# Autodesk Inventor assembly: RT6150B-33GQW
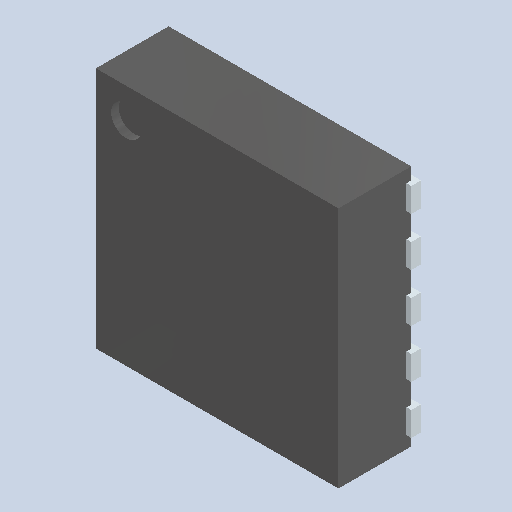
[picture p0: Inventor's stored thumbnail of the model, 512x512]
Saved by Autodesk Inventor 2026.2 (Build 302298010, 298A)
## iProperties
Created: 2026-10
Part Number: RT6150B-33GQW
Document SubType Name: Assembly
Designer: mel
Author: mel
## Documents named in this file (4)
- D:\travail\année 2026-2027\1 sti2d IT\poubelle à verre\raspberry-pico-2-microcontroller-rp2350-1.snapshot.5\raspberry_pico_2\raspberry_pico_2\RT6150B-33GQW.iam
- D:\travail\année 2026-2027\1 sti2d IT\poubelle à verre\raspberry-pico-2-microcontroller-rp2350-1.snapshot.5\raspberry_pico_2\raspberry_pico_2\Body.ipt
- D:\travail\année 2026-2027\1 sti2d IT\poubelle à verre\raspberry-pico-2-microcontroller-rp2350-1.snapshot.5\raspberry_pico_2\raspberry_pico_2\ThermalPin.ipt
- D:\travail\année 2026-2027\1 sti2d IT\poubelle à verre\raspberry-pico-2-microcontroller-rp2350-1.snapshot.5\raspberry_pico_2\raspberry_pico_2\PinsArrayLR010.iam
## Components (3 placed, 3 different names)
1. 2759
2. 2760
3. 2771 [sub-assembly]
